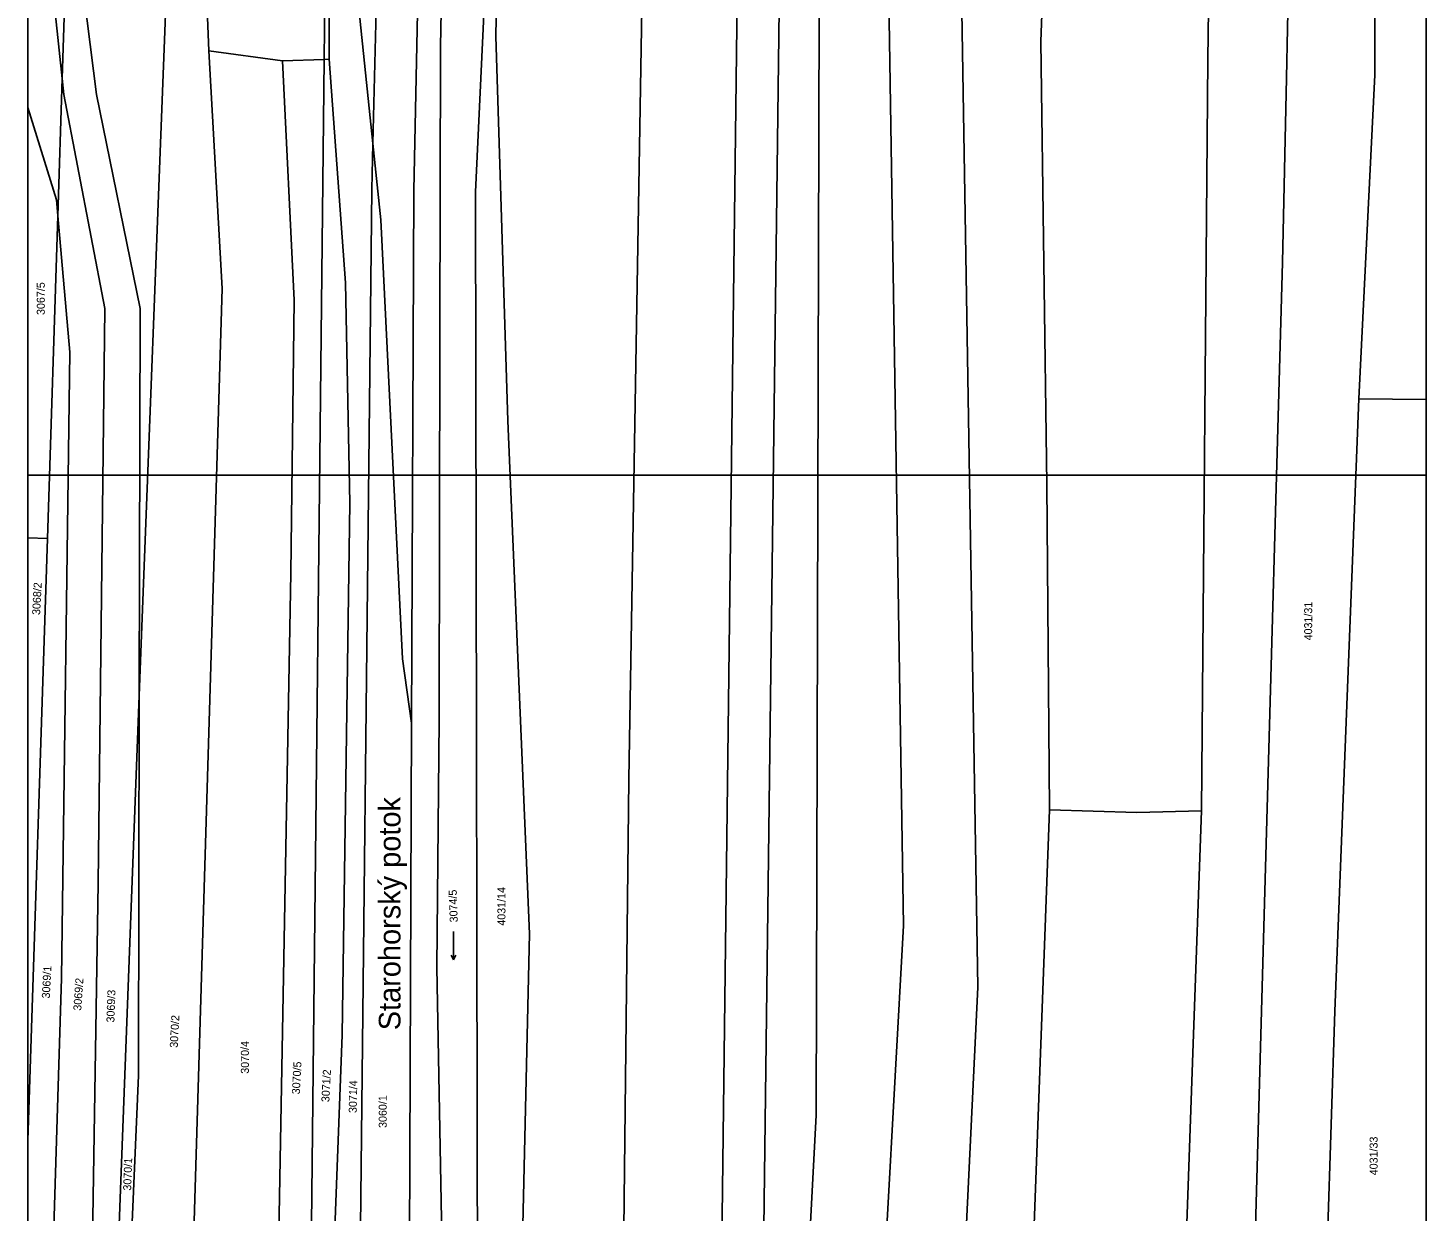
# Model space of a CAD drawing. Extents: x -534410 to -534262, y -1190162 to -1189584.
# Drawn here: x -534410.1 to -534261.6, y -1189872.7 to -1189746.9 of the extents above; entities that cross this region are included whole.
import ezdxf

# ---------------------------------------------------------------- set-up
doc = ezdxf.new("R2010")
doc.units = 0
for name, color, linetype in [('_KN_Povodí_Moravy', 7, 'Continuous'), ('_N_osa', 7, 'Continuous'), ('_rámeček', 7, 'Continuous'), ('_rámeček_mřížka', 7, 'Continuous'), ('_tenka', 7, 'Continuous'), ('Hranice parcel', 7, 'Continuous'), ('Parcelní čísla', 7, 'Continuous'), ('Pop  PČ popisy', 7, 'Continuous')]:
    doc.layers.add(name, color=color, linetype=linetype)

msp = doc.modelspace()

# ---------------------------------------------------------------- linework, layer by layer
at = {"layer": '_KN_Povodí_Moravy'}
for p, q in [((-534367.77, -1189697.34), (-534369.14, -1189764.19)), ((-534369.14, -1189764.19), (-534369.38, -1189820.8)), ((-534369.38, -1189820.8), (-534369.75, -1189908.47))]:
    msp.add_line(p, q, dxfattribs=at)
msp.add_lwpolyline([(-534362.34, -1189901.56), (-534362.6, -1189764.35), (-534359.48, -1189697.97)], dxfattribs=at)
at = {"layer": '_N_osa'}
msp.add_lwpolyline([(-534351.95, -1189940.72), (-534356.84, -1189928.92), (-534363.29, -1189912.04), (-534365.92, -1189888.84), (-534366.71, -1189846.73), (-534366.46, -1189820.49), (-534366.39, -1189779.5), (-534366.3, -1189748.87), (-534365.06, -1189684.89), (-534363.19, -1189653.56), (-534361.33, -1189627.82)], dxfattribs=at)
at = {"layer": '_rámeček'}
msp.add_line((-534410.13, -1189584.47), (-534410.13, -1190161.97), dxfattribs=at)
msp.add_lwpolyline([(-534410.13, -1190161.97), (-534261.63, -1190161.97), (-534261.63, -1189584.47)], dxfattribs=at)
for points in [[(-534410.13, -1189689.47), (-534261.63, -1189689.47), (-534261.63, -1189794.47), (-534410.13, -1189794.47)], [(-534410.13, -1189794.47), (-534261.63, -1189794.47), (-534261.63, -1189899.47), (-534410.13, -1189899.47)]]:
    msp.add_lwpolyline(points, close=True, dxfattribs=at)
at = {"layer": '_rámeček_mřížka'}
for p, q in [((-534410.13, -1189584.47), (-534410.13, -1190161.97)), ((-534407.13, -1189794.47), (-534410.13, -1189794.47)), ((-534264.63, -1189794.47), (-534261.63, -1189794.47))]:
    msp.add_line(p, q, dxfattribs=at)
msp.add_lwpolyline([(-534410.13, -1190161.97), (-534261.63, -1190161.97), (-534261.63, -1189584.47)], dxfattribs=at)
at = {"layer": '_tenka'}
for p, q in [((-534364.93, -1189842.94), (-534364.93, -1189845.94)), ((-534364.93, -1189845.94), (-534365.18, -1189845.46)), ((-534364.93, -1189845.94), (-534364.67, -1189845.46))]:
    msp.add_line(p, q, dxfattribs=at)
at = {"layer": 'Hranice parcel'}
for p, q in [((-534371.04, -1189658.4), (-534373.49, -1189759.21)), ((-534378.67, -1189750.28), (-534377.8, -1189671.05)), ((-534369.14, -1189764.19), (-534367.77, -1189697.34)), ((-534406.48, -1189752.31), (-534404.82, -1189701)), ((-534398.3, -1189817.87), (-534394.19, -1189710.57)), ((-534390.92, -1189749.37), (-534383.09, -1189750.44)), ((-534383.09, -1189750.44), (-534378.67, -1189750.28)), ((-534378.12, -1189750.26), (-534378.67, -1189750.28)), ((-534406.95, -1189766.9), (-534406.48, -1189752.31)), ((-534373.49, -1189759.21), (-534373.61, -1189764.09)), ((-534369.38, -1189820.8), (-534369.14, -1189764.19)), ((-534408.06, -1189801.17), (-534406.95, -1189766.9)), ((-534261.63, -1189786.4), (-534268.75, -1189786.35)), ((-534410.13, -1189801.12), (-534408.06, -1189801.17)), ((-534410.13, -1189865.16), (-534408.06, -1189801.17)), ((-534403.19, -1189945.91), (-534398.3, -1189817.87)), ((-534369.75, -1189908.47), (-534369.38, -1189820.8)), ((-534305.77, -1189942.29), (-534301.62, -1189830.03))]:
    msp.add_line(p, q, dxfattribs=at)
for points in [[(-534347.07, -1189935.15), (-534347.12, -1189900.1), (-534346.3, -1189826.77), (-534344.77, -1189736.43), (-534342.85, -1189658.07), (-534338.33, -1189584.47)], [(-534338.84, -1189942.48), (-534336.49, -1189881.83), (-534334.78, -1189743.85), (-534331.69, -1189634.65)], [(-534334.89, -1189942.46), (-534332.03, -1189880.06), (-534330.32, -1189744.92), (-534328.5, -1189646.74), (-534327.9, -1189634.55)], [(-534330.63, -1189942.43), (-534326.4, -1189862.47), (-534326.07, -1189744.82), (-534325.13, -1189646.79), (-534324.46, -1189634.65)], [(-534373.49, -1189759.21), (-534375.27, -1189742.09), (-534373.87, -1189702.99), (-534373.87, -1189662.03), (-534374.42, -1189646.7)], [(-534323.08, -1189942.39), (-534320.68, -1189906.36), (-534317.14, -1189842.3), (-534318.66, -1189746.11), (-534316.5, -1189653.71)], [(-534314.47, -1189942.34), (-534311.69, -1189899.83), (-534309.24, -1189848.85), (-534310.92, -1189745.14), (-534308.43, -1189653.71)], [(-534378.12, -1189750.26), (-534378.12, -1189746.17), (-534376.49, -1189693.82), (-534377.8, -1189671.05)], [(-534301.62, -1189830.03), (-534301.89, -1189795.41), (-534302.54, -1189748.37), (-534300.35, -1189689.47)], [(-534285.48, -1189830.14), (-534284.81, -1189750.3), (-534284, -1189688.91)], [(-534284.68, -1189943.89), (-534282.37, -1189910.46), (-534280.12, -1189888.37), (-534278.75, -1189838.65), (-534276.86, -1189771.85), (-534276.43, -1189752.24), (-534275.19, -1189689.29)], [(-534268.75, -1189786.35), (-534267.08, -1189751.92), (-534266.88, -1189688.91)], [(-534359.48, -1189697.97), (-534362.6, -1189764.35), (-534362.34, -1189901.56)], [(-534359.48, -1189697.97), (-534360.42, -1189747.8), (-534359.17, -1189788.69), (-534356.86, -1189843.2), (-534358.53, -1189915.98)], [(-534406.48, -1189752.31), (-534408.29, -1189735.19), (-534406.08, -1189700.59)], [(-534398.3, -1189817.87), (-534398.2, -1189776.76), (-534402.83, -1189754), (-534404.51, -1189740.82), (-534402.1, -1189701.89)], [(-534390.92, -1189749.37), (-534391.09, -1189744.93), (-534393.26, -1189731.27), (-534393.26, -1189715.05), (-534394.19, -1189710.57)], [(-534395.93, -1189955.06), (-534393.76, -1189916.2), (-534389.49, -1189774.63), (-534390.92, -1189749.37)], [(-534385.61, -1189919.11), (-534380.06, -1189877.29), (-534378.67, -1189750.28)], [(-534385.61, -1189919.11), (-534383.81, -1189892.54), (-534382.22, -1189804.86), (-534381.85, -1189775.86), (-534383.09, -1189750.44)], [(-534383.94, -1189956.8), (-534379.19, -1189918.48), (-534376.74, -1189853.94), (-534375.92, -1189797.44), (-534376.41, -1189774.02), (-534378.12, -1189750.26)], [(-534406.13, -1189942), (-534403.45, -1189886.77), (-534402.68, -1189837.82), (-534401.95, -1189776.76), (-534406.3, -1189754), (-534406.48, -1189752.31)], [(-534410.13, -1189755.37), (-534407.1, -1189765.2), (-534406.95, -1189766.9)], [(-534369.38, -1189820.8), (-534370.35, -1189813.98), (-534372.65, -1189767.31), (-534373.49, -1189759.21)], [(-534373.61, -1189764.09), (-534375.04, -1189897.07), (-534384.28, -1189963.65)], [(-534410.13, -1189932.79), (-534408.16, -1189899.66), (-534406.57, -1189847.9), (-534405.68, -1189781.38), (-534406.95, -1189766.9)], [(-534276.35, -1189944.53), (-534272.88, -1189899.59), (-534271.33, -1189851.42), (-534268.75, -1189786.35)], [(-534403.19, -1189945.91), (-534400.52, -1189907.49), (-534398.39, -1189858.23), (-534398.3, -1189817.87)], [(-534301.62, -1189830.03), (-534292.36, -1189830.3), (-534285.48, -1189830.14)], [(-534289.92, -1189943.5), (-534288.56, -1189917.25), (-534286.37, -1189854.83), (-534285.48, -1189830.14)]]:
    msp.add_lwpolyline(points, dxfattribs=at)

# ---------------------------------------------------------------- texts
at = {"layer": '_tenka'}
msp.add_text('3074/5', height=0.85, rotation=92, dxfattribs=at).set_placement((-534364.47, -1189841.96))
at = {"layer": 'Parcelní čísla'}
for s, rotation, p in [('3067/5', 90, (-534408.34, -1189777.43)), ('3068/2', 87, (-534408.84, -1189809.33)), ('4031/31', 90, (-534273.72, -1189812.01)), ('4031/14', 90, (-534359.41, -1189842.33)), ('3069/1', 87, (-534407.81, -1189850.08)), ('3069/2', 86, (-534404.47, -1189851.38)), ('3069/3', 88, (-534400.95, -1189852.63)), ('3070/2', 87, (-534394.22, -1189855.32)), ('3070/4', 90, (-534386.66, -1189858.06)), ('3070/5', 87, (-534381.25, -1189860.26)), ('3071/2', 87, (-534378.12, -1189861.1)), ('3071/4', 89, (-534375.21, -1189862.24)), ('3060/1', 90, (-534372.02, -1189863.82)), ('4031/33', 90, (-534266.77, -1189868.85)), ('3070/1', 88, (-534399.17, -1189870.49))]:
    msp.add_text(s, height=0.85, rotation=rotation, dxfattribs=at).set_placement(p)
at = {"layer": 'Pop  PČ popisy'}
msp.add_text('Starohorský potok', height=2.3, rotation=90, dxfattribs=at).set_placement((-534370.56, -1189853.44))

doc.saveas('drawing.dxf')
